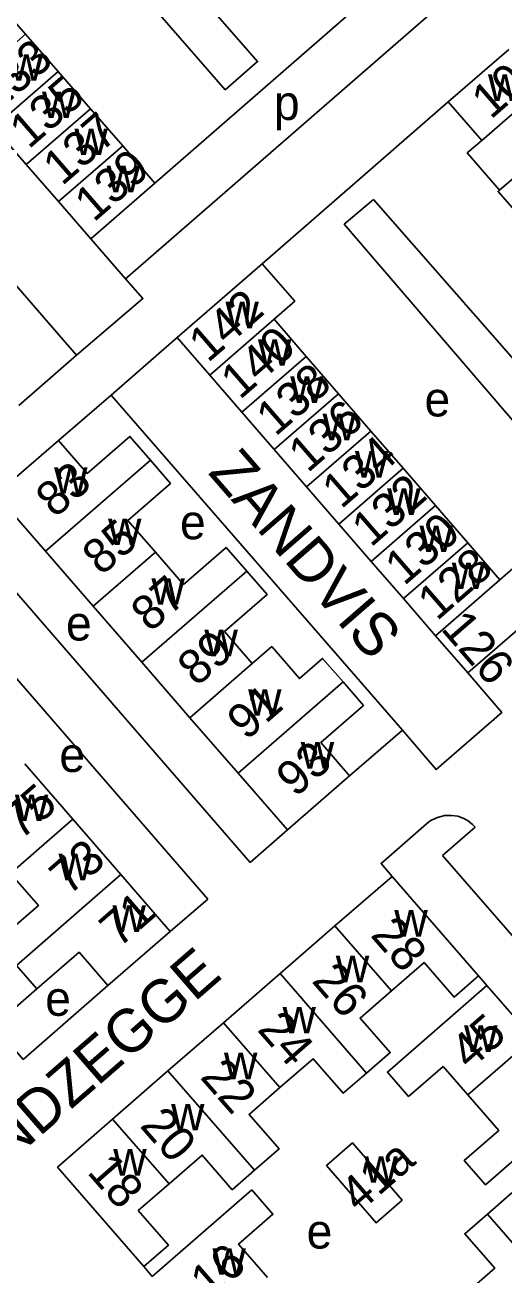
# Model space of a CAD drawing. Extents: x 155854 to 157362, y 383621 to 384685.
# Drawn here: x 156498.5 to 156553.9, y 384187.6 to 384332.2 of the extents above; entities that cross this region are included whole.
import ezdxf

# ---------------------------------------------------------------- set-up
doc = ezdxf.new("R2010")
doc.units = 0
for name, color, linetype in [('BLT_Basislijn', 7, 'Continuous'), ('BLT_Bebouwing', 7, 'Continuous'), ('BLT_Centroide', 7, 'Continuous'), ('BLT_Huisnummer', 7, 'Continuous'), ('BLT_Huisnummer_ tussenligend', 7, 'Continuous'), ('BLT_Huisnummer_reeks', 7, 'Continuous'), ('BLT_Onderverdeling_panden', 7, 'Continuous'), ('BLT_Straatnaam', 7, 'Continuous')]:
    doc.layers.add(name, color=color, linetype=linetype)

msp = doc.modelspace()

# ---------------------------------------------------------------- linework, layer by layer
at = {"layer": 'BLT_Basislijn'}
for p, q in [((156489.82, 384361.43), (156521.66, 384324.72)), ((156525.13, 384324.03), (156535.85, 384333.36)), ((156513.54, 384313.95), (156525.13, 384324.03)), ((156535.2, 384312.67), (156547.48, 384323.35)), ((156525.95, 384304.62), (156535.2, 384312.67)), ((156570.81, 384275.55), (156538.82, 384312.06)), ((156491.44, 384309.04), (156502.92, 384295.83)), ((156508.49, 384289.41), (156516.11, 384296.1)), ((156502.92, 384295.83), (156504.47, 384294.05)), ((156497.78, 384288.23), (156504.47, 384294.05)), ((156508.49, 384289.41), (156502.37, 384284.18)), ((156542.17, 384250.64), (156508.49, 384289.41)), ((156490.89, 384274.12), (156524.57, 384235.35)), ((156485.98, 384269.86), (156519.66, 384231.09)), ((156536.05, 384245.38), (156542.17, 384250.64)), ((156524.57, 384235.35), (156528.87, 384239.1)), ((156546.83, 384236.14), (156550.6, 384239.42)), ((156546.83, 384236.14), (156577.91, 384200.36)), ((156519.66, 384231.09), (156515.31, 384227.37)), ((156550.97, 384222.22), (156551.95, 384221.09)), ((156508.11, 384221.1), (156498.31, 384212.56)), ((156513.22, 384187.45), (156512.26, 384188.59))]:
    msp.add_line(p, q, dxfattribs=at)
for points in [[(156493.41, 384364.56), (156525.42, 384328), (156521.66, 384324.72)], [(156510.15, 384302.85), (156550.84, 384338.29)], [(156567.1, 384272.32), (156535.44, 384309.18), (156538.82, 384312.06)], [(156510.15, 384302.85), (156506.12, 384307.5)], [(156504.47, 384294.05), (156512.16, 384300.59), (156510.15, 384302.85)], [(156542.17, 384250.64), (156546.06, 384246.08), (156553.69, 384252.71), (156549.74, 384257.27)], [(156540.97, 384233.73), (156539.71, 384235.24), (156544.96, 384239.82)], [(156544.96, 384239.82), (156545.38, 384240.15), (156546.13, 384240.52), (156547.04, 384240.79), (156547.85, 384240.79), (156548.57, 384240.71), (156549.27, 384240.44), (156549.77, 384240.15), (156550.28, 384239.74), (156550.6, 384239.42)]]:
    msp.add_lwpolyline(points, dxfattribs=at)
at = {"layer": 'BLT_Bebouwing'}
for p, q in [((156547.48, 384323.35), (156554.48, 384329.42)), ((156547.48, 384323.35), (156551.35, 384318.88)), ((156498.65, 384316.1), (156494.9, 384320.41)), ((156502.39, 384311.8), (156498.65, 384316.1)), ((156506.12, 384307.5), (156502.39, 384311.8)), ((156516.11, 384296.1), (156525.95, 384304.62)), ((156502.37, 384284.18), (156495.16, 384277.93)), ((156495.16, 384277.93), (156500.88, 384271.35)), ((156500.88, 384271.35), (156506.41, 384264.98)), ((156506.41, 384264.98), (156512.02, 384258.51)), ((156512.02, 384258.51), (156517.59, 384252.09)), ((156517.59, 384252.09), (156523.16, 384245.68)), ((156498.48, 384246.76), (156504.05, 384240.34)), ((156523.16, 384245.68), (156528.87, 384239.1)), ((156528.87, 384239.1), (156536.05, 384245.38)), ((156504.05, 384240.34), (156509.61, 384233.93)), ((156509.61, 384233.93), (156515.31, 384227.37)), ((156540.97, 384233.73), (156534.37, 384227.99)), ((156550.97, 384222.22), (156540.97, 384233.73)), ((156534.37, 384227.99), (156528.03, 384222.49)), ((156528.03, 384222.49), (156521.47, 384216.79)), ((156551.95, 384221.09), (156557.25, 384214.99)), ((156521.47, 384216.79), (156515.05, 384211.22)), ((156515.05, 384211.22), (156508.64, 384205.64)), ((156508.64, 384205.64), (156502.26, 384200.1)), ((156512.26, 384188.59), (156502.26, 384200.1))]:
    msp.add_line(p, q, dxfattribs=at)
for points in [[(156494.84, 384335.47), (156498.58, 384331.17)], [(156498.58, 384331.17), (156502.33, 384326.86)], [(156502.33, 384326.86), (156506.07, 384322.55)], [(156506.07, 384322.55), (156509.81, 384318.24)], [(156509.81, 384318.24), (156513.54, 384313.95)], [(156551.35, 384318.88), (156549.68, 384317.44), (156553.42, 384313.14)], [(156513.54, 384313.95), (156506.12, 384307.5)], [(156553.42, 384313.14), (156553.25, 384312.99), (156556.99, 384308.69), (156558.82, 384310.28)], [(156525.95, 384304.62), (156529.71, 384300.29), (156527.32, 384298.21)], [(156527.32, 384298.21), (156531.05, 384293.9)], [(156519.88, 384291.74), (156516.11, 384296.1)], [(156531.05, 384293.9), (156534.79, 384289.58)], [(156523.61, 384287.43), (156519.88, 384291.74)], [(156534.79, 384289.58), (156538.53, 384285.26)], [(156527.35, 384283.12), (156523.61, 384287.43)], [(156513.01, 384281.9), (156510.64, 384284.64), (156505.7, 384280.35), (156502.37, 384284.18)], [(156538.53, 384285.26), (156542.27, 384280.95)], [(156531.09, 384278.8), (156527.35, 384283.12)], [(156513.61, 384271.24), (156510.42, 384274.91), (156515.36, 384279.2), (156513.01, 384281.9)], [(156542.27, 384280.95), (156546, 384276.64)], [(156534.83, 384274.48), (156531.09, 384278.8)], [(156546, 384276.64), (156549.74, 384272.33)], [(156538.56, 384270.18), (156534.83, 384274.48)], [(156524.16, 384269.06), (156521.78, 384271.8), (156516.84, 384267.51), (156513.61, 384271.24)], [(156549.74, 384272.33), (156553.45, 384268.04)], [(156553.45, 384268.04), (156558.28, 384272.24), (156562.05, 384267.91)], [(156542.3, 384265.87), (156538.56, 384270.18)], [(156524.79, 384258.35), (156521.58, 384262.06), (156526.51, 384266.35), (156524.16, 384269.06)], [(156562.05, 384267.91), (156549.74, 384257.27)], [(156546.01, 384261.58), (156542.3, 384265.87)], [(156549.74, 384257.27), (156546.01, 384261.58)], [(156535.3, 384256.23), (156532.94, 384258.95), (156530.26, 384256.62), (156527.05, 384260.32), (156524.79, 384258.35)], [(156536.05, 384245.38), (156532.72, 384249.22), (156537.66, 384253.51), (156535.3, 384256.23)], [(156496.85, 384234.08), (156500.06, 384230.38), (156495.17, 384226.14)], [(156515.31, 384227.37), (156508.11, 384221.1)], [(156508.11, 384221.1), (156504.77, 384224.95), (156499.88, 384220.71)], [(156540.91, 384220.49), (156544.68, 384223.77), (156546.41, 384221.77), (156548.15, 384219.77), (156550.97, 384222.22)], [(156499.88, 384220.71), (156494.96, 384216.43), (156498.31, 384212.56)], [(156551.95, 384221.09), (156540.44, 384211.09), (156542.89, 384208.27), (156546.88, 384211.74), (156549.75, 384208.44)], [(156538.03, 384210.98), (156540.76, 384213.34), (156537.28, 384217.34), (156540.91, 384220.49)], [(156528.01, 384209.3), (156531.85, 384212.63), (156535.32, 384208.63), (156538.03, 384210.98)], [(156525.08, 384199.73), (156527.91, 384202.19), (156524.44, 384206.19), (156528.01, 384209.3)], [(156549.75, 384208.44), (156553.31, 384204.34), (156549.32, 384200.87), (156551.78, 384198.05), (156563.28, 384208.05)], [(156515.18, 384198.15), (156519.01, 384201.48), (156522.49, 384197.48), (156525.08, 384199.73)], [(156512.26, 384188.59), (156515.1, 384191.06), (156511.62, 384195.06), (156515.18, 384198.15)], [(156526.57, 384187.3), (156523.21, 384191.17), (156527.2, 384194.63), (156524.74, 384197.46), (156513.22, 384187.45)], [(156561.88, 384196.24), (156558.28, 384193.11), (156554.83, 384197.1), (156552.01, 384194.65)], [(156552.01, 384194.65), (156549.39, 384192.38), (156552.85, 384188.4), (156549.05, 384185.09)]]:
    msp.add_lwpolyline(points, dxfattribs=at)
msp.add_lwpolyline([(156533.39, 384200.27), (156536.41, 384202.9), (156542.13, 384196.27), (156539.12, 384193.65)], close=True, dxfattribs=at)
at = {"layer": 'BLT_Onderverdeling_panden'}
for p, q in [((156491.16, 384324.72), (156498.58, 384331.17)), ((156494.9, 384320.41), (156502.33, 384326.86)), ((156551.35, 384318.88), (156558.35, 384324.96)), ((156498.65, 384316.1), (156506.07, 384322.55)), ((156553.42, 384313.14), (156562.08, 384320.66)), ((156502.39, 384311.8), (156509.81, 384318.24)), ((156527.32, 384298.21), (156519.88, 384291.74)), ((156531.05, 384293.9), (156523.61, 384287.43)), ((156534.79, 384289.58), (156527.35, 384283.12)), ((156538.53, 384285.26), (156531.09, 384278.8)), ((156500.88, 384271.35), (156513.01, 384281.9)), ((156542.27, 384280.95), (156534.83, 384274.48)), ((156546, 384276.64), (156538.56, 384270.18)), ((156549.74, 384272.33), (156542.3, 384265.87)), ((156506.41, 384264.98), (156513.61, 384271.24)), ((156512.02, 384258.51), (156524.16, 384269.06)), ((156546.01, 384261.58), (156553.45, 384268.04)), ((156517.59, 384252.09), (156524.79, 384258.35)), ((156523.16, 384245.68), (156535.3, 384256.23)), ((156496.85, 384234.08), (156504.05, 384240.34)), ((156497.53, 384223.42), (156509.61, 384233.93)), ((156540.91, 384220.49), (156534.37, 384227.99)), ((156499.88, 384220.71), (156497.53, 384223.42)), ((156528.03, 384222.49), (156538.03, 384210.98)), ((156521.47, 384216.79), (156528.01, 384209.3)), ((156557.25, 384214.99), (156549.75, 384208.44)), ((156515.05, 384211.22), (156525.08, 384199.73)), ((156508.64, 384205.64), (156515.18, 384198.15)), ((156562, 384183.14), (156552.01, 384194.65))]:
    msp.add_line(p, q, dxfattribs=at)

# ---------------------------------------------------------------- texts
at = {"layer": 'BLT_Centroide'}
for s, p in [('w', (156496.74, 384325.78)), ('w', (156552.08, 384323.44)), ('w', (156500.48, 384321.47)), ('p', (156527.31, 384321.25)), ('w', (156504.23, 384317.19)), ('w', (156507.96, 384312.88)), ('w', (156521.7, 384297.16)), ('w', (156525.46, 384292.81)), ('w', (156529.2, 384288.5)), ('e', (156544.73, 384286.95)), ('w', (156532.94, 384284.19)), ('w', (156536.68, 384279.88)), ('w', (156501.88, 384278)), ('w', (156540.41, 384275.56)), ('e', (156516.44, 384272.74)), ('w', (156508.12, 384272.06)), ('w', (156544.15, 384271.25)), ('w', (156547.88, 384266.97)), ('w', (156513.14, 384265.16)), ('e', (156503.25, 384261.02)), ('w', (156519.27, 384259.19)), ('w', (156524.32, 384252.31)), ('e', (156502.48, 384245.81)), ('w', (156530.41, 384246.2)), ('w', (156497.34, 384240.12)), ('w', (156502.39, 384233.28)), ('w', (156508.63, 384227.31)), ('w', (156541.24, 384226.75)), ('w', (156534.47, 384221.47)), ('e', (156500.85, 384217.6)), ('w', (156528.3, 384215.56)), ('w', (156549.31, 384213.41)), ('w', (156521.53, 384210.25)), ('w', (156515.41, 384204.34)), ('w', (156508.72, 384199.11)), ('w', (156537.77, 384198.28)), ('e', (156531.09, 384190.67)), ('w', (156520.2, 384187.64))]:
    msp.add_text(s, height=4, dxfattribs=at).set_placement(p)
at = {"layer": 'BLT_Huisnummer'}
for s, rotation, p in [('104', 40.9897, (156552.39, 384321.23)), ('135', 40.9795, (156498.94, 384317.8)), ('139', 40.9795, (156506.46, 384309.33)), ('142', 40.9804, (156519.67, 384293.08)), ('138', 40.9804, (156527.48, 384284.55)), ('134', 40.9804, (156535.09, 384276.15)), ('83', 40.9833, (156501.97, 384275.1)), ('130', 40.9804, (156542.37, 384267.27)), ('89', 40.9833, (156518.37, 384255.6)), ('93', 40.9833, (156529.79, 384242.78)), ('75', 40.9833, (156497.99, 384237.84)), ('71', 40.9833, (156509.36, 384225.37)), ('28', 311.1173, (156538.38, 384226.88)), ('45', 41.088, (156549.95, 384211.22)), ('22', 311.1173, (156518.66, 384210.46)), ('41a', 40.9729, (156537.15, 384194.72)), ('18', 311.1173, (156505.59, 384199.47)), ('16', 41.044, (156519.87, 384184.63))]:
    msp.add_text(s, height=4, rotation=rotation, dxfattribs=at).set_placement(p)
at = {"layer": 'BLT_Huisnummer_ tussenligend'}
for s, rotation, p in [('133', 40.9795, (156495.24, 384322.06)), ('137', 40.9795, (156502.8, 384313.55)), ('140', 40.9804, (156523.37, 384288.81)), ('136', 40.9804, (156531.21, 384280.33)), ('132', 40.9804, (156538.52, 384271.72)), ('85', 40.9833, (156507.35, 384268.43)), ('128', 40.9804, (156546.16, 384263.21)), ('87', 40.9833, (156512.98, 384261.88)), ('91', 40.9833, (156524.11, 384249.36)), ('73', 40.9833, (156503.57, 384231.42)), ('26', 311.1173, (156531.58, 384221.58)), ('24', 311.1173, (156525.28, 384215.95)), ('20', 311.1173, (156511.69, 384204.83))]:
    msp.add_text(s, height=4, rotation=rotation, dxfattribs=at).set_placement(p)
at = {"layer": 'BLT_Huisnummer_reeks'}
msp.add_text('126', height=4, rotation=310.8946, dxfattribs=at).set_placement((156546.52, 384262.33))
at = {"layer": 'BLT_Straatnaam'}
for s, rotation, p in [('ZANDVIS', 310.9816, (156519.59, 384280.4)), ('ZANDZEGGE', 40.9824, (156490.07, 384194.77))]:
    msp.add_text(s, height=5, rotation=rotation, dxfattribs=at).set_placement(p)

doc.saveas('drawing.dxf')
